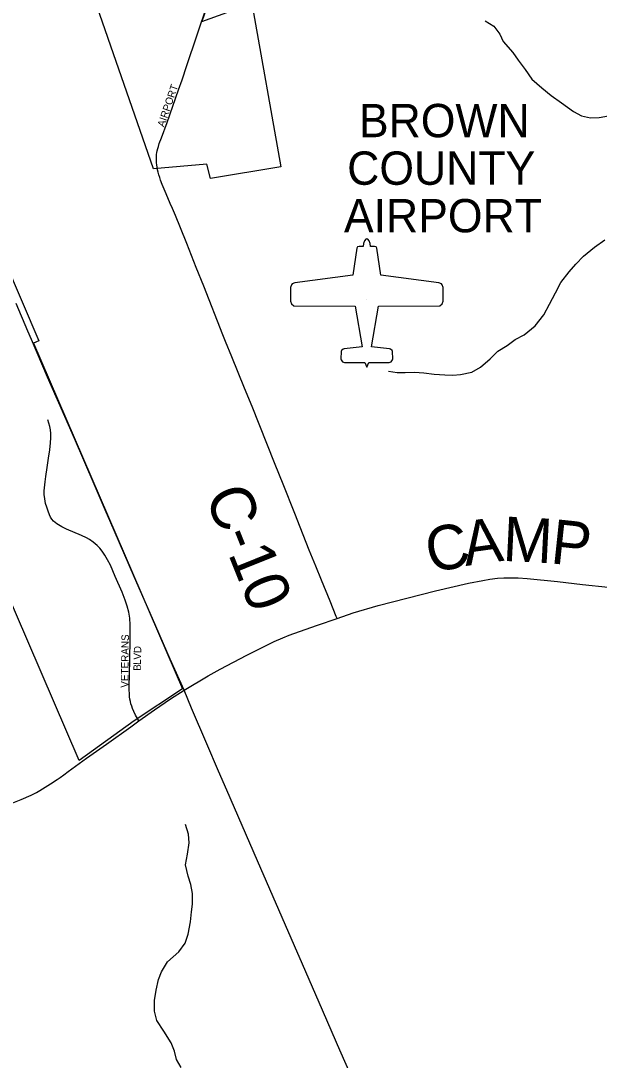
# Model space of a CAD drawing. Extents: x 1451455 to 1749751, y 218250 to 574981.
# Drawn here: x 1572855 to 1576761, y 318985 to 326004 of the extents above; entities that cross this region are included whole.
import ezdxf

# ---------------------------------------------------------------- set-up
doc = ezdxf.new("R2010")
doc.units = 0
for name, color, linetype in [('GM_X_Airport_Class_3', 7, 'Continuous'), ('GM_X_Airport_Location_Class_3', 7, 'Continuous'), ('GM_X_Airport_Text_Class_3', 7, 'Continuous'), ('GM_X_City_Street', 7, 'Continuous'), ('GM_X_City_Street_Text', 7, 'Continuous'), ('GM_X_Corporation', 7, 'Continuous'), ('GM_X_County_Road', 7, 'Continuous'), ('GM_X_County_Road_Text', 7, 'Continuous'), ('GM_X_Minor_River', 7, 'Continuous'), ('GM_X_US_Route', 7, 'Continuous')]:
    doc.layers.add(name, color=color, linetype=linetype)

msp = doc.modelspace()

# ---------------------------------------------------------------- linework, layer by layer
at = {"layer": 'GM_X_Airport_Class_3'}
for points in [[(1575191.6, 324532.7), (1575184, 324529.4), (1575175.8, 324517.3), (1575169.7, 324499.2), (1575166.5, 324480.9), (1575139.6, 324481), (1575129.3, 324477.4), (1575123.8, 324469.5), (1575097.3, 324285.4), (1574705.6, 324235.3), (1574688.3, 324227.7), (1574682, 324220.6), (1574676.6, 324202.5), (1574676.4, 324111.7), (1574682.7, 324092.2), (1574699.2, 324080.1), (1575112.2, 324077.4), (1575160.2, 323803), (1575038.7, 323789.3), (1575031.7, 323787.5), (1575020.7, 323778.3), (1575017.7, 323771.8), (1575016.5, 323721.5), (1575017.7, 323713.8), (1575026.7, 323701.3), (1575041.3, 323696.5), (1575178.8, 323696.1), (1575191.6, 323664.1)], [(1575191.6, 323664.1), (1575204.5, 323696.1), (1575342, 323696.5), (1575356.6, 323701.3), (1575365.6, 323713.8), (1575366.8, 323721.4), (1575365.6, 323771.8), (1575362.6, 323778.3), (1575351.6, 323787.5), (1575344.6, 323789.3), (1575223.1, 323803), (1575271.1, 324077.4), (1575684.1, 324080.1), (1575700.6, 324092.2), (1575706.9, 324111.7), (1575706.7, 324202.5), (1575701.3, 324220.6), (1575695, 324227.7), (1575677.7, 324235.3), (1575286, 324285.4), (1575259.5, 324469.5), (1575254, 324477.4), (1575243.7, 324481), (1575216.8, 324480.9), (1575213.6, 324499.2), (1575207.5, 324517.3), (1575199.3, 324529.4), (1575191.6, 324532.7)]]:
    msp.add_lwpolyline(points, dxfattribs=at)
at = {"layer": 'GM_X_Airport_Location_Class_3'}
msp.add_line((1575191.6, 324122.4), (1575191.6, 324122.4), dxfattribs=at)
at = {"layer": 'GM_X_City_Street'}
for points in [[(1573773.6, 325030.7), (1573771.8, 325045.3), (1573770.4, 325061.3), (1573770.4, 325076.3), (1573771.3, 325088.6), (1573772.2, 325101.3), (1573773.8, 325114.7), (1573776.3, 325127.2), (1573779.5, 325140.9), (1573784.1, 325155.9), (1573790.2, 325175.1), (1573803.9, 325213.9), (1573843, 325317.7), (1573920.6, 325537.4), (1573944.2, 325605.3), (1573976.3, 325701.7), (1574252.3, 326525.5)], [(1573651.2, 321275.7), (1573629.9, 321314.3), (1573618.1, 321338.7), (1573609.4, 321360.4), (1573603.7, 321374.6), (1573598.6, 321390.5), (1573594.6, 321406.4), (1573591.2, 321422.9), (1573588.9, 321439.4), (1573587.8, 321455.4), (1573587.6, 321490.6), (1573589.6, 321610.6), (1573590.6, 321668.3), (1573593.9, 321848.7), (1573593.7, 321924), (1573591, 321969.5), (1573584.6, 322011.2), (1573574.1, 322051.9), (1573560.5, 322092), (1573538.6, 322146.6), (1573492.7, 322251.9), (1573459.9, 322326.9), (1573440.7, 322364.8), (1573422.7, 322395.6), (1573404, 322422.1), (1573387.4, 322441.9), (1573369.4, 322460.5), (1573342.4, 322483.8), (1573317.6, 322501), (1573298.8, 322511.8), (1573264, 322528.6), (1573164.3, 322571.1), (1573131.5, 322586.9), (1573108.4, 322600.4), (1573097.2, 322607.9), (1573086.6, 322616.4), (1573076.6, 322625.2), (1573065.2, 322637.7), (1573055.7, 322651.9), (1573048.1, 322667), (1573039, 322692.4), (1573029.7, 322720), (1573022.2, 322745.2), (1573016.1, 322776), (1573012.6, 322805.1), (1573012.6, 322829.8), (1573019.7, 322891.7), (1573023.8, 322927.6), (1573032.4, 322986.4), (1573042, 323051.2), (1573050.1, 323106.3), (1573055.9, 323154.9), (1573058.2, 323187.3), (1573058.2, 323216.4), (1573056, 323242.1), (1573051.5, 323264.1), (1573038.1, 323309.4)]]:
    msp.add_lwpolyline(points, dxfattribs=at)
at = {"layer": 'GM_X_Corporation'}
for points in [[(1574114.2, 326102.6), (1574077.9, 325998.7), (1574416.2, 326121.8), (1574610.7, 325018.6), (1574136, 324938.4), (1574112.2, 325035.2), (1573750.7, 325003.4), (1573137, 326772.8)], [(1571933.2, 326277.8), (1572976.6, 323842), (1572941.4, 323828.2), (1573947, 321492.6), (1573619.3, 321277.6), (1573248.1, 321008.8), (1572392.3, 322992.4)]]:
    msp.add_lwpolyline(points, dxfattribs=at)
at = {"layer": 'GM_X_County_Road'}
for points in [[(1573879.1, 324737), (1573864.4, 324771.2), (1573836.5, 324836.2), (1573809.6, 324899), (1573799.2, 324926.9), (1573792.9, 324944.9), (1573786.2, 324964.2), (1573781.7, 324981.3), (1573778.5, 324997.9), (1573775.5, 325015.5), (1573773.6, 325030.7)], [(1574991, 321967.9), (1574985.6, 321981.3), (1574944.7, 322084.2), (1574884.9, 322226.2), (1574847.6, 322320.7), (1574803.4, 322430.2), (1574741.6, 322585.6), (1574704.9, 322676.8), (1574625.8, 322874.7), (1574572.6, 323008.8), (1574463.9, 323279.6), (1574416.9, 323398.5), (1574365.1, 323522.6), (1574279.8, 323735.7), (1574237.5, 323838.8), (1574219.5, 323884.5), (1574091.1, 324211), (1574039.9, 324338.9), (1573975.2, 324499.6), (1573932.4, 324605.9), (1573898.4, 324689.7), (1573879.1, 324737)], [(1574991, 321967.9), (1575100.3, 322005.3), (1575269, 322055.7), (1575655.1, 322153.9), (1575878.8, 322205.5), (1575975.4, 322225.4), (1576021.7, 322233.2), (1576073.4, 322239.3), (1576116, 322242.5), (1576162.2, 322243.3), (1576214, 322241.4), (1576273.9, 322237.2), (1576479.6, 322216.5), (1576649.2, 322198.1), (1576822.1, 322179.5), (1577095.4, 322143.8), (1577354.5, 322106.1)], [(1573957.3, 321484.4), (1574120, 321581.5), (1574200.6, 321625.7), (1574380.5, 321720.8), (1574489.3, 321775), (1574566.3, 321812), (1574623.6, 321837), (1574666.3, 321854.2), (1574737.2, 321880.4), (1574858.2, 321922.3), (1574991, 321967.9)], [(1573651.2, 321275.7), (1573651.4, 321275.8), (1573758.1, 321351.7), (1573866.6, 321426.1), (1573957.3, 321484.4)], [(1573175, 320933.7), (1573298.4, 321024.7), (1573433, 321119.6), (1573598.8, 321236.9), (1573651.2, 321275.7)], [(1571712.8, 320299.5), (1571759.7, 320314.8), (1571846.1, 320343), (1571917.4, 320368), (1571979.2, 320388.5), (1572101, 320437.1), (1572182.8, 320470.9), (1572331.1, 320532.7), (1572546.6, 320620.7), (1572756.8, 320704.1), (1572858.2, 320746.4), (1572923.7, 320774.9), (1572960.4, 320793.3), (1572983.6, 320806.7), (1573018.4, 320827.6), (1573055.4, 320850.3), (1573099.9, 320880.4), (1573119.9, 320893.4), (1573145.3, 320911.9), (1573175, 320933.7)]]:
    msp.add_lwpolyline(points, dxfattribs=at)
at = {"layer": 'GM_X_Minor_River'}
for points in [[(1575990.2, 326004.6), (1576049.7, 325967.6), (1576090.8, 325914.8), (1576112, 325864.4), (1576176.9, 325789.2), (1576214.1, 325738.5), (1576261.1, 325675.6), (1576306.1, 325610.8), (1576373.2, 325551.6), (1576436.5, 325500.5), (1576507.7, 325451.2), (1576586.8, 325391.9), (1576642.4, 325362.9), (1576702.2, 325347.9), (1576760.3, 325351), (1576824.6, 325362), (1576902.7, 325366.8), (1576956.6, 325359.9), (1577026.8, 325366.8), (1577084.9, 325367.8)], [(1575337.7, 323638.5), (1575395.6, 323629.6), (1575451.6, 323628.7), (1575513.7, 323631.7), (1575577.7, 323626.7), (1575645.6, 323617.6), (1575717.6, 323612.4), (1575771.6, 323611.5), (1575823.7, 323614.7), (1575900, 323631.5), (1575958.6, 323664.6), (1576025.6, 323721.7), (1576076.4, 323773), (1576139.1, 323812), (1576193.8, 323851.2), (1576254.4, 323884.3), (1576329.4, 323945.2), (1576386.6, 324018.5), (1576425.8, 324090), (1576467.1, 324167.5), (1576502.2, 324237), (1576559.4, 324308.2), (1576604.3, 324361.6), (1576655.2, 324414.9), (1576730.3, 324475.8), (1576799.1, 324524.8)], [(1574015.3, 320038), (1574014.5, 320110.1), (1574003.5, 320170.4), (1573984.5, 320226.8), (1573967.8, 320303.1), (1573981, 320377), (1573992.2, 320453), (1573987.2, 320511.1), (1573966.3, 320577.6)], [(1573937.2, 318935.6), (1573906.1, 318990.2), (1573893, 319046.5), (1573870, 319102.9), (1573821.3, 319181.8), (1573772.5, 319252.6), (1573757.6, 319317), (1573756.8, 319387.1), (1573767.9, 319457), (1573785.1, 319528.8), (1573804, 319582.6), (1573845, 319648.1), (1573922.1, 319717), (1573965, 319774.4), (1573986, 319836.2), (1574001.4, 319920.1), (1574008.5, 319986), (1574015.3, 320038)]]:
    msp.add_lwpolyline(points, dxfattribs=at)
at = {"layer": 'GM_X_US_Route'}
for points in [[(1572926.7, 323852.2), (1572902.7, 323908.2), (1572822.4, 324094.7)], [(1573094.1, 323464.3), (1573035.9, 323597.7), (1572926.7, 323852.2)], [(1573957.3, 321484.4), (1573863.3, 321693.6), (1573744.9, 321967.5), (1573622.9, 322243.5), (1573485.6, 322562.9), (1573425.3, 322701.2), (1573350.2, 322876), (1573216.8, 323182.8), (1573112, 323423.3), (1573094.1, 323464.3)], [(1575085.5, 318878.5), (1575008.5, 319052.6), (1574868.9, 319374.7), (1574757, 319633.8), (1574703.9, 319757.4), (1574453.7, 320332), (1574246.8, 320807.4), (1574190.7, 320936.9), (1574112, 321120.9), (1574007.8, 321361.8), (1573957.3, 321484.4)]]:
    msp.add_lwpolyline(points, dxfattribs=at)

# ---------------------------------------------------------------- texts
at = {"layer": 'GM_X_Airport_Text_Class_3'}
for s, p in [('BROWN', (1575138.3, 325218)), ('COUNTY', (1575059.1, 324896.8)), ('AIRPORT', (1575037.1, 324575.6))]:
    msp.add_text(s, height=225, rotation=0.00001, dxfattribs=at).set_placement(p)
at = {"layer": 'GM_X_City_Street_Text'}
for s, rotation, p in [('AIRPORT', 71.25765, (1573822.6, 325282.7)), ('VETERANS', 89.22475, (1573580.1, 321499.9)), ('V', 88.16366, (1573666.2, 321688.9)), ('D', 87.89022, (1573667.6, 321732.8)), ('B', 89.63567, (1573665.1, 321614.4)), ('L', 88.63379, (1573665.4, 321653.8))]:
    msp.add_text(s, height=50, rotation=rotation, dxfattribs=at).set_placement(p)
at = {"layer": 'GM_X_County_Road_Text'}
for s, rotation, p in [('C-10', 291.86629, (1574095.3, 322798.6)), ('A', 7.86582, (1575858.7, 322321.9)), ('M', 357.11459, (1576105.4, 322357.4)), ('P', 353.97359, (1576426.2, 322341.3)), ('C', 12.12092, (1575623.6, 322271.2))]:
    msp.add_text(s, height=300, rotation=rotation, dxfattribs=at).set_placement(p)

doc.saveas('drawing.dxf')
